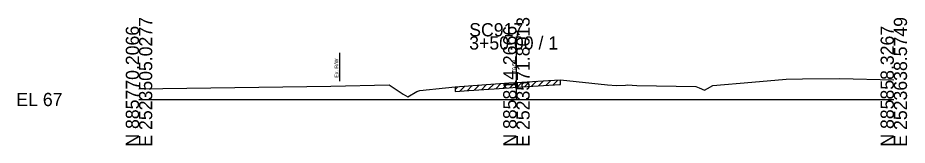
# Model space of a CAD drawing. Extents: x -26 to 218, y -10 to 12021.
# Drawn here: x -25.7 to 162.8, y 3490.3 to 3517.3 of the extents above; entities that cross this region are included whole.
import ezdxf

# ---------------------------------------------------------------- set-up
doc = ezdxf.new("R2010")
doc.units = 0
for name, color, linetype in [('RD_GPK_XS_Cell', 7, 'Continuous'), ('RD_XS_ExGround', 7, 'Continuous'), ('RD_XS_ExPaveRet', 7, 'Continuous'), ('RD_XS_ExRW', 7, 'Continuous'), ('RD_XS_TX_Elev_EX', 7, 'Continuous')]:
    doc.layers.add(name, color=color, linetype=linetype)

msp = doc.modelspace()

# ---------------------------------------------------------------- linework, layer by layer
at = {"layer": 'RD_GPK_XS_Cell'}
for p, q in [((80, 3500), (80, 3513.38)), ((0, 3500), (80, 3500)), ((80, 3500), (160, 3500))]:
    msp.add_line(p, q, dxfattribs=at)
at = {"layer": 'RD_XS_ExGround'}
for p, q in [((40.67, 3502.82), (53.04, 3503.08)), ((53.04, 3503.08), (56.01, 3501.11)), ((69.84, 3502.88), (78.43, 3503.5)), ((78.43, 3503.5), (80, 3503.59)), ((80, 3503.59), (86.83, 3504.01)), ((86.83, 3504.01), (89.38, 3504.16)), ((89.38, 3504.16), (99.32, 3503.14)), ((99.32, 3503.14), (101.19, 3503)), ((101.19, 3503), (103.09, 3503.05)), ((103.09, 3503.05), (103.53, 3503.13)), ((103.53, 3503.13), (105.55, 3502.99)), ((105.55, 3502.99), (118.03, 3502.77)), ((120.53, 3502.31), (121.61, 3502.97)), ((121.61, 3502.97), (129.93, 3503.67)), ((129.93, 3503.67), (137.21, 3504.3)), ((137.21, 3504.3), (140.61, 3504.36)), ((140.61, 3504.36), (148.46, 3504.46)), ((148.46, 3504.46), (160, 3504.18)), ((0, 3502.28), (40.67, 3502.82)), ((56.01, 3501.11), (56.98, 3500.57)), ((56.98, 3500.57), (58.91, 3501.67)), ((58.91, 3501.67), (59.51, 3501.93)), ((59.51, 3501.93), (64.97, 3502.46)), ((64.97, 3502.46), (67.01, 3502.67)), ((67.01, 3502.67), (69.84, 3502.88)), ((118.03, 3502.77), (118.71, 3502.5)), ((118.71, 3502.5), (119.9, 3502)), ((119.9, 3502), (120.53, 3502.31))]:
    msp.add_line(p, q, dxfattribs=at)
at = {"layer": 'RD_XS_ExPaveRet'}
for p, q in [((69.54, 3501.86), (70.62, 3502.94)), ((71.06, 3501.97), (72.14, 3503.05)), ((72.58, 3502.08), (73.66, 3503.16)), ((74.11, 3502.18), (75.19, 3503.26)), ((75.63, 3502.29), (76.71, 3503.37)), ((77.16, 3502.4), (78.24, 3503.48)), ((78.68, 3502.51), (79.74, 3503.58)), ((80.06, 3502.6), (86.89, 3503.01)), ((80.18, 3502.6), (81.25, 3503.67)), ((81.69, 3502.7), (82.76, 3503.76)), ((83.2, 3502.79), (84.26, 3503.86)), ((84.7, 3502.88), (85.77, 3503.95)), ((86.21, 3502.97), (87.28, 3504.04)), ((86.89, 3503.01), (89.38, 3503.16)), ((87.72, 3503.06), (88.78, 3504.13)), ((89.22, 3503.15), (89.38, 3503.31)), ((89.38, 3503.16), (89.38, 3504.16)), ((67.01, 3502.15), (67.56, 3502.71)), ((67.01, 3502.67), (67.01, 3501.67)), ((67.01, 3501.67), (69.92, 3501.88)), ((68.01, 3501.74), (69.09, 3502.82)), ((69.92, 3501.88), (78.5, 3502.5)), ((78.5, 3502.5), (80.06, 3502.6))]:
    msp.add_line(p, q, dxfattribs=at)
at = {"layer": 'RD_XS_ExRW'}
msp.add_line((42.5, 3509.86), (42.5, 3503.86), dxfattribs=at)

# ---------------------------------------------------------------- texts
at = {"layer": 'RD_GPK_XS_Cell'}
for s, p in [('E 2523505.0277', (2.8, 3490)), ('E 2523571.8013', (82.8, 3490)), ('E 2523638.5749', (162.8, 3490)), ('N 885770.2066', (0, 3490)), ('N 885814.2666', (80, 3490)), ('N 885858.3267', (160, 3490))]:
    msp.add_text(s, height=2.8, rotation=90, dxfattribs=at).set_placement(p)
for s, p in [('SC917', (70, 3513.38)), ('3+50.00 / 1', (70, 3510.58)), ('EL 67', (-26, 3498.6))]:
    msp.add_text(s, height=2.8, dxfattribs=at).set_placement(p)
at = {"layer": 'RD_XS_ExRW'}
msp.add_text('Ex. R/W ', height=0.8, rotation=90, dxfattribs=at).set_placement((42.25, 3504.64))
at = {"layer": 'RD_XS_TX_Elev_EX'}
msp.add_text('70.59', height=0.8, rotation=90, dxfattribs=at).set_placement((79.9, 3505.59))

doc.saveas('drawing.dxf')
